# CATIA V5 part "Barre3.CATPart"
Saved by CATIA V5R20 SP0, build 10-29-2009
Part number: Barre3
Publications: "Barre3", "Pivot3/2", "Pivot 3/0"
Bounding box of the stored display mesh (mm): x -14.631 to 8.121, y -80.465 to -3.769, z -5 to 5
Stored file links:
  C:\Users\Admin\Desktop\IAO\Barre3.CATPart
  C:\Users\Admin\Desktop\IAO\Skl_4barres.CATProduct
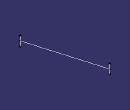
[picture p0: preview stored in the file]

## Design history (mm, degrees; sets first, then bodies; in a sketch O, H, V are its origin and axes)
Set1
  Point1 "Point C": linked copy from another document
  Point2 "Point B": linked copy from another document
  Plane1 "Plan ref": linked copy from another document
Set2
  Line1: type PtPt, FirstPoint Point1, SecondPoint Point2
  Line2: type Normal, RefPoint Point1, RefSkin Plane1, Start -5, End 5
  Line3: type Normal, RefPoint Point2, RefSkin Plane1, Start -5, End 5
Body1 (main body)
